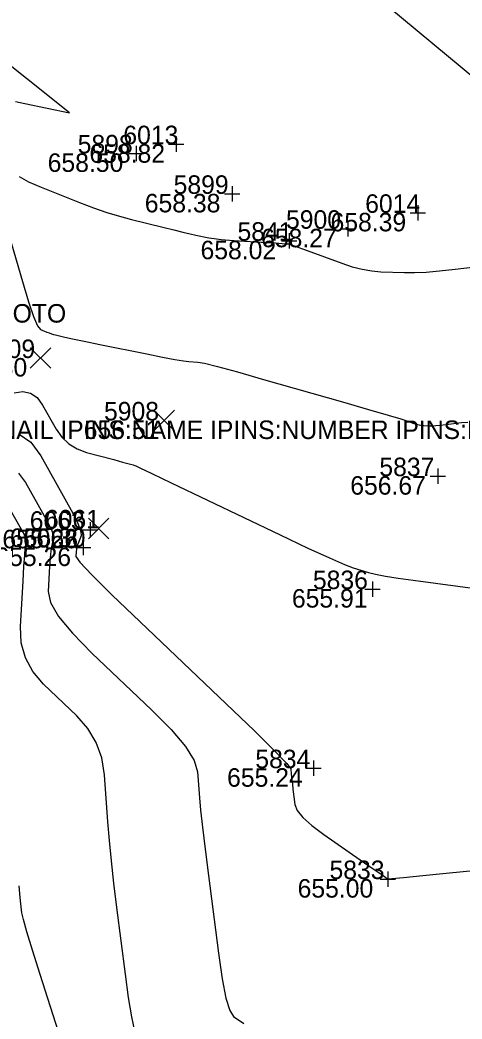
# Model space of a CAD drawing. Extents: x 2129350 to 2137777, y 657588 to 659885.
# Drawn here: x 2132845.8 to 2132874.5, y 658928.5 to 658993.3 of the extents above; entities that cross this region are included whole.
import ezdxf

# ---------------------------------------------------------------- set-up
doc = ezdxf.new("R2010")
doc.units = 0
for name, color, linetype in [('DT_X_Contour_Major', 7, 'Continuous'), ('DT_X_Contour_Minor', 7, 'Continuous'), ('SV_X_Random_Point', 7, 'Continuous'), ('SV_X_Shot_Marker', 7, 'Continuous'), ('SV_X_Text_Comment', 7, 'Continuous'), ('SV_X_Text_Elevation', 7, 'Continuous'), ('SV_X_Text_Name', 7, 'Continuous')]:
    doc.layers.add(name, color=color, linetype=linetype)

msp = doc.modelspace()

# ---------------------------------------------------------------- linework, layer by layer
at = {"layer": 'DT_X_Contour_Major'}
msp.add_lwpolyline([(2132845.742, 658966.43), (2132846.494, 658965.896), (2132847.136, 658965.021), (2132848.705, 658962.232), (2132849.212, 658961.297), (2132849.555, 658960.584), (2132849.736, 658960.091), (2132849.753, 658959.82), (2132849.58, 658959.392), (2132849.523, 658959.236), (2132849.48, 658959.088), (2132849.451, 658958.948), (2132849.437, 658958.816), (2132849.418, 658958.476), (2132849.673, 658958.115), (2132850.453, 658957.289), (2132851.758, 658955.998), (2132853.588, 658954.241), (2132859.167, 658948.935), (2132860.999, 658947.178), (2132862.31, 658945.888), (2132863.1, 658945.064), (2132863.37, 658944.707), (2132863.394, 658944.376), (2132863.408, 658944.221), (2132863.431, 658944.005), (2132863.464, 658943.729), (2132863.506, 658943.391), (2132863.632, 658942.409), (2132863.784, 658942.01), (2132864.147, 658941.55), (2132864.719, 658941.03), (2132865.502, 658940.448), (2132867.869, 658938.816), (2132868.646, 658938.28), (2132869.202, 658937.897), (2132869.536, 658937.666), (2132869.65, 658937.589), (2132869.657, 658937.585), (2132869.66, 658937.584), (2132869.663, 658937.583), (2132869.668, 658937.581), (2132869.675, 658937.58), (2132869.927, 658937.603), (2132870.678, 658937.675), (2132871.927, 658937.796), (2132873.674, 658937.965), (2132878.999, 658938.481)], dxfattribs=at)
at = {"layer": 'DT_X_Contour_Minor'}
for points in [[(2132877.411, 658987.728), (2132864.847, 658998.185)], [(2132845.498, 658987.986), (2132846.096, 658987.859), (2132849.001, 658987.264), (2132843.406, 658991.719)], [(2132845.735, 658983.139), (2132846.348, 658982.792), (2132847.17, 658982.432), (2132849.642, 658981.451), (2132850.549, 658981.106), (2132851.414, 658980.805), (2132852.238, 658980.55), (2132853.022, 658980.339), (2132855.056, 658979.837), (2132855.762, 658979.664), (2132856.356, 658979.523), (2132856.838, 658979.412), (2132857.207, 658979.333), (2132858.04, 658979.163), (2132858.398, 658979.102), (2132858.844, 658979.048), (2132859.379, 658979), (2132860.002, 658978.959), (2132861.785, 658978.857), (2132862.375, 658978.821), (2132862.81, 658978.793), (2132863.088, 658978.77), (2132863.211, 658978.754), (2132863.331, 658978.72), (2132863.458, 658978.677), (2132864.198, 658978.41), (2132866.666, 658977.508), (2132867.347, 658977.283), (2132867.998, 658977.116), (2132868.619, 658977.008), (2132869.212, 658976.958), (2132870.752, 658976.903), (2132871.389, 658976.901), (2132872.147, 658976.935), (2132873.024, 658977.006), (2132874.022, 658977.113), (2132876.841, 658977.448)], [(2132844.78, 658980.325), (2132845.941, 658976.326), (2132846.342, 658975.006), (2132846.672, 658974.045), (2132846.932, 658973.445), (2132847.122, 658973.204), (2132847.534, 658973.04), (2132847.685, 658972.983), (2132847.829, 658972.933), (2132847.966, 658972.89), (2132848.097, 658972.855), (2132848.436, 658972.771), (2132848.69, 658972.715), (2132849.198, 658972.608), (2132849.959, 658972.45), (2132850.974, 658972.242), (2132854.02, 658971.621), (2132855.047, 658971.415), (2132855.843, 658971.265), (2132856.408, 658971.17), (2132856.743, 658971.13), (2132857.327, 658971.096), (2132857.759, 658971.016), (2132858.615, 658970.803), (2132859.896, 658970.455), (2132861.602, 658969.973), (2132866.717, 658968.508), (2132868.417, 658968.02), (2132869.68, 658967.653), (2132870.507, 658967.407), (2132870.898, 658967.284), (2132871.357, 658967.116), (2132871.525, 658967.06), (2132871.686, 658967.019), (2132871.84, 658966.992), (2132871.987, 658966.98), (2132872.368, 658966.966), (2132872.541, 658966.968), (2132872.774, 658966.981), (2132873.068, 658967.008), (2132873.421, 658967.047), (2132874.444, 658967.169), (2132874.845, 658967.19)], [(2132845.404, 658969.098), (2132845.968, 658969.189), (2132846.465, 658969.087), (2132846.894, 658968.792), (2132847.256, 658968.306), (2132848.13, 658966.752), (2132848.499, 658966.22), (2132848.952, 658965.79), (2132849.488, 658965.462), (2132850.107, 658965.236), (2132851.87, 658964.769), (2132852.451, 658964.614), (2132852.873, 658964.5), (2132853.135, 658964.427), (2132853.238, 658964.395), (2132853.3, 658964.364), (2132853.571, 658964.235), (2132854.336, 658963.87), (2132855.594, 658963.268), (2132862.681, 658959.885), (2132864.477, 658959.035), (2132865.866, 658958.396), (2132866.848, 658957.967), (2132867.422, 658957.749), (2132868.412, 658957.447), (2132868.871, 658957.33), (2132869.509, 658957.207), (2132870.324, 658957.077), (2132871.316, 658956.94), (2132874.2, 658956.567), (2132875.329, 658956.4)], [(2132845.696, 658963.897), (2132846.149, 658963.28), (2132847.255, 658961.314), (2132847.612, 658960.655), (2132847.854, 658960.152), (2132847.981, 658959.805), (2132847.993, 658959.614), (2132847.872, 658959.312), (2132847.828, 658959.136), (2132847.786, 658958.835), (2132847.748, 658958.408), (2132847.712, 658957.856), (2132847.621, 658956.216), (2132847.772, 658955.505), (2132848.295, 658954.603), (2132849.189, 658953.51), (2132850.454, 658952.226), (2132854.323, 658948.546), (2132855.599, 658947.259), (2132856.523, 658946.158), (2132857.096, 658945.244), (2132857.318, 658944.516), (2132857.442, 658942.823), (2132857.513, 658942.032), (2132857.632, 658940.929), (2132857.801, 658939.513), (2132858.018, 658937.786), (2132858.661, 658932.762), (2132858.903, 658931.092), (2132859.148, 658929.85), (2132859.396, 658929.035), (2132859.646, 658928.648), (2132860.316, 658928.186)], [(2132853.26, 658927.593), (2132853.048, 658928.622), (2132852.838, 658929.889), (2132852.63, 658931.395), (2132852.075, 658935.729), (2132851.882, 658937.294), (2132851.72, 658938.739), (2132851.59, 658940.065), (2132851.491, 658941.271), (2132851.267, 658944.325), (2132851.092, 658945.424), (2132850.736, 658946.429), (2132850.199, 658947.34), (2132849.48, 658948.157), (2132847.32, 658950.211), (2132846.619, 658951.023), (2132846.136, 658951.917), (2132845.871, 658952.895), (2132845.824, 658953.956), (2132845.987, 658956.896), (2132846.044, 658957.868), (2132846.093, 658958.582), (2132846.132, 658959.036), (2132846.163, 658959.232), (2132846.234, 658959.407), (2132846.227, 658959.518), (2132846.153, 658959.72), (2132846.012, 658960.012), (2132845.805, 658960.396), (2132845.161, 658961.539)], [(2132848.601, 658926.645), (2132847.098, 658931.373), (2132846.602, 658932.952), (2132846.239, 658934.144), (2132846.01, 658934.948), (2132845.915, 658935.365), (2132845.839, 658935.959), (2132845.798, 658936.361), (2132845.735, 658937.122)]]:
    msp.add_lwpolyline(points, dxfattribs=at)
at = {"layer": 'SV_X_Random_Point'}
for p, q in [((2132846.445, 658970.691), (2132847.779, 658972.025)), ((2132846.445, 658972.025), (2132847.779, 658970.691)), ((2132854.485, 658966.642), (2132855.819, 658967.976)), ((2132854.485, 658967.976), (2132855.819, 658966.642)), ((2132850.227, 658959.639), (2132851.561, 658960.975)), ((2132850.227, 658960.975), (2132851.561, 658959.639))]:
    msp.add_line(p, q, dxfattribs=at)
at = {"layer": 'SV_X_Shot_Marker'}
for p, q in [((2132855.924, 658985.727), (2132855.924, 658984.727)), ((2132853.33, 658985.13), (2132853.33, 658984.13)), ((2132855.424, 658985.227), (2132856.424, 658985.227)), ((2132855.924, 658985.227), (2132855.924, 658985.227)), ((2132852.83, 658984.63), (2132853.83, 658984.63)), ((2132853.33, 658984.63), (2132853.33, 658984.63)), ((2132859.556, 658982.506), (2132859.556, 658981.506)), ((2132859.056, 658982.006), (2132860.056, 658982.006)), ((2132859.556, 658982.006), (2132859.556, 658982.006)), ((2132871.612, 658981.275), (2132871.612, 658980.275)), ((2132871.112, 658980.775), (2132872.112, 658980.775)), ((2132871.612, 658980.775), (2132871.612, 658980.775)), ((2132867.058, 658980.242), (2132867.058, 658979.242)), ((2132863.25, 658979.465), (2132863.25, 658978.465)), ((2132866.558, 658979.742), (2132867.558, 658979.742)), ((2132867.058, 658979.742), (2132867.058, 658979.742)), ((2132862.75, 658978.965), (2132863.75, 658978.965)), ((2132863.25, 658978.965), (2132863.25, 658978.965)), ((2132872.4, 658963.697), (2132873.4, 658963.697)), ((2132872.9, 658964.197), (2132872.9, 658963.197)), ((2132872.9, 658963.697), (2132872.9, 658963.697)), ((2132850.342, 658960.718), (2132850.342, 658959.718)), ((2132849.842, 658960.218), (2132850.842, 658960.218)), ((2132850.342, 658960.218), (2132850.342, 658960.218)), ((2132849.389, 658959.068), (2132850.389, 658959.068)), ((2132849.889, 658959.568), (2132849.889, 658958.568)), ((2132849.889, 658959.068), (2132849.889, 658959.068)), ((2132868.662, 658956.871), (2132868.662, 658955.871)), ((2132868.162, 658956.371), (2132869.162, 658956.371)), ((2132868.662, 658956.371), (2132868.662, 658956.371)), ((2132864.84, 658945.253), (2132864.84, 658944.253)), ((2132864.34, 658944.753), (2132865.34, 658944.753)), ((2132864.84, 658944.753), (2132864.84, 658944.753)), ((2132869.664, 658938.062), (2132869.664, 658937.062)), ((2132869.164, 658937.562), (2132870.164, 658937.562)), ((2132869.664, 658937.562), (2132869.664, 658937.562))]:
    msp.add_line(p, q, dxfattribs=at)

# ---------------------------------------------------------------- texts
at = {"layer": 'SV_X_Text_Comment'}
for s, p in [('T:TYPE MAPLE T:PHOTO', (2132829.705, 658973.656)), ('IPINS:SIZE NAIL IPINS:NAME IPINS:NUMBER IPINS:NOTE IPINS:PHOTO', (2132835.741, 658966.105))]:
    msp.add_text(s, height=1.2, dxfattribs=at).set_placement(p)
at = {"layer": 'SV_X_Text_Elevation'}
for s, p in [('658.82', (2132850.293, 658984.027)), ('658.50', (2132847.585, 658983.43)), ('658.38', (2132853.887, 658980.806)), ('658.39', (2132865.943, 658979.575)), ('658.27', (2132861.436, 658978.542)), ('658.02', (2132857.505, 658977.765)), ('656.80', (2132841.349, 658970.158)), ('656.51', (2132849.926, 658966.109)), ('656.67', (2132867.222, 658962.497)), ('655.26', (2132844.645, 658959.018)), ('655.30', (2132845.131, 658959.107)), ('655.26', (2132844.192, 658957.868)), ('655.91', (2132863.436, 658955.171)), ('655.24', (2132859.228, 658943.553)), ('655.00', (2132863.806, 658936.362))]:
    msp.add_text(s, height=1.2, dxfattribs=at).set_placement(p)
at = {"layer": 'SV_X_Text_Name'}
for s, p in [('6013', (2132852.495, 658985.227)), ('5898', (2132849.532, 658984.63)), ('5899', (2132855.758, 658982.006)), ('6014', (2132868.192, 658980.775)), ('5900', (2132863.052, 658979.742)), ('5841', (2132859.905, 658978.965)), ('5909', (2132843.2, 658971.358)), ('5908', (2132851.24, 658967.309)), ('5837', (2132869.111, 658963.697)), ('6063', (2132846.421, 658960.218)), ('6061', (2132847.407, 658960.307)), ('6062', (2132845.977, 658959.068)), ('5836', (2132864.798, 658956.371)), ('5834', (2132861.061, 658944.753)), ('5833', (2132865.875, 658937.562))]:
    msp.add_text(s, height=1.2, dxfattribs=at).set_placement(p)

doc.saveas('drawing.dxf')
